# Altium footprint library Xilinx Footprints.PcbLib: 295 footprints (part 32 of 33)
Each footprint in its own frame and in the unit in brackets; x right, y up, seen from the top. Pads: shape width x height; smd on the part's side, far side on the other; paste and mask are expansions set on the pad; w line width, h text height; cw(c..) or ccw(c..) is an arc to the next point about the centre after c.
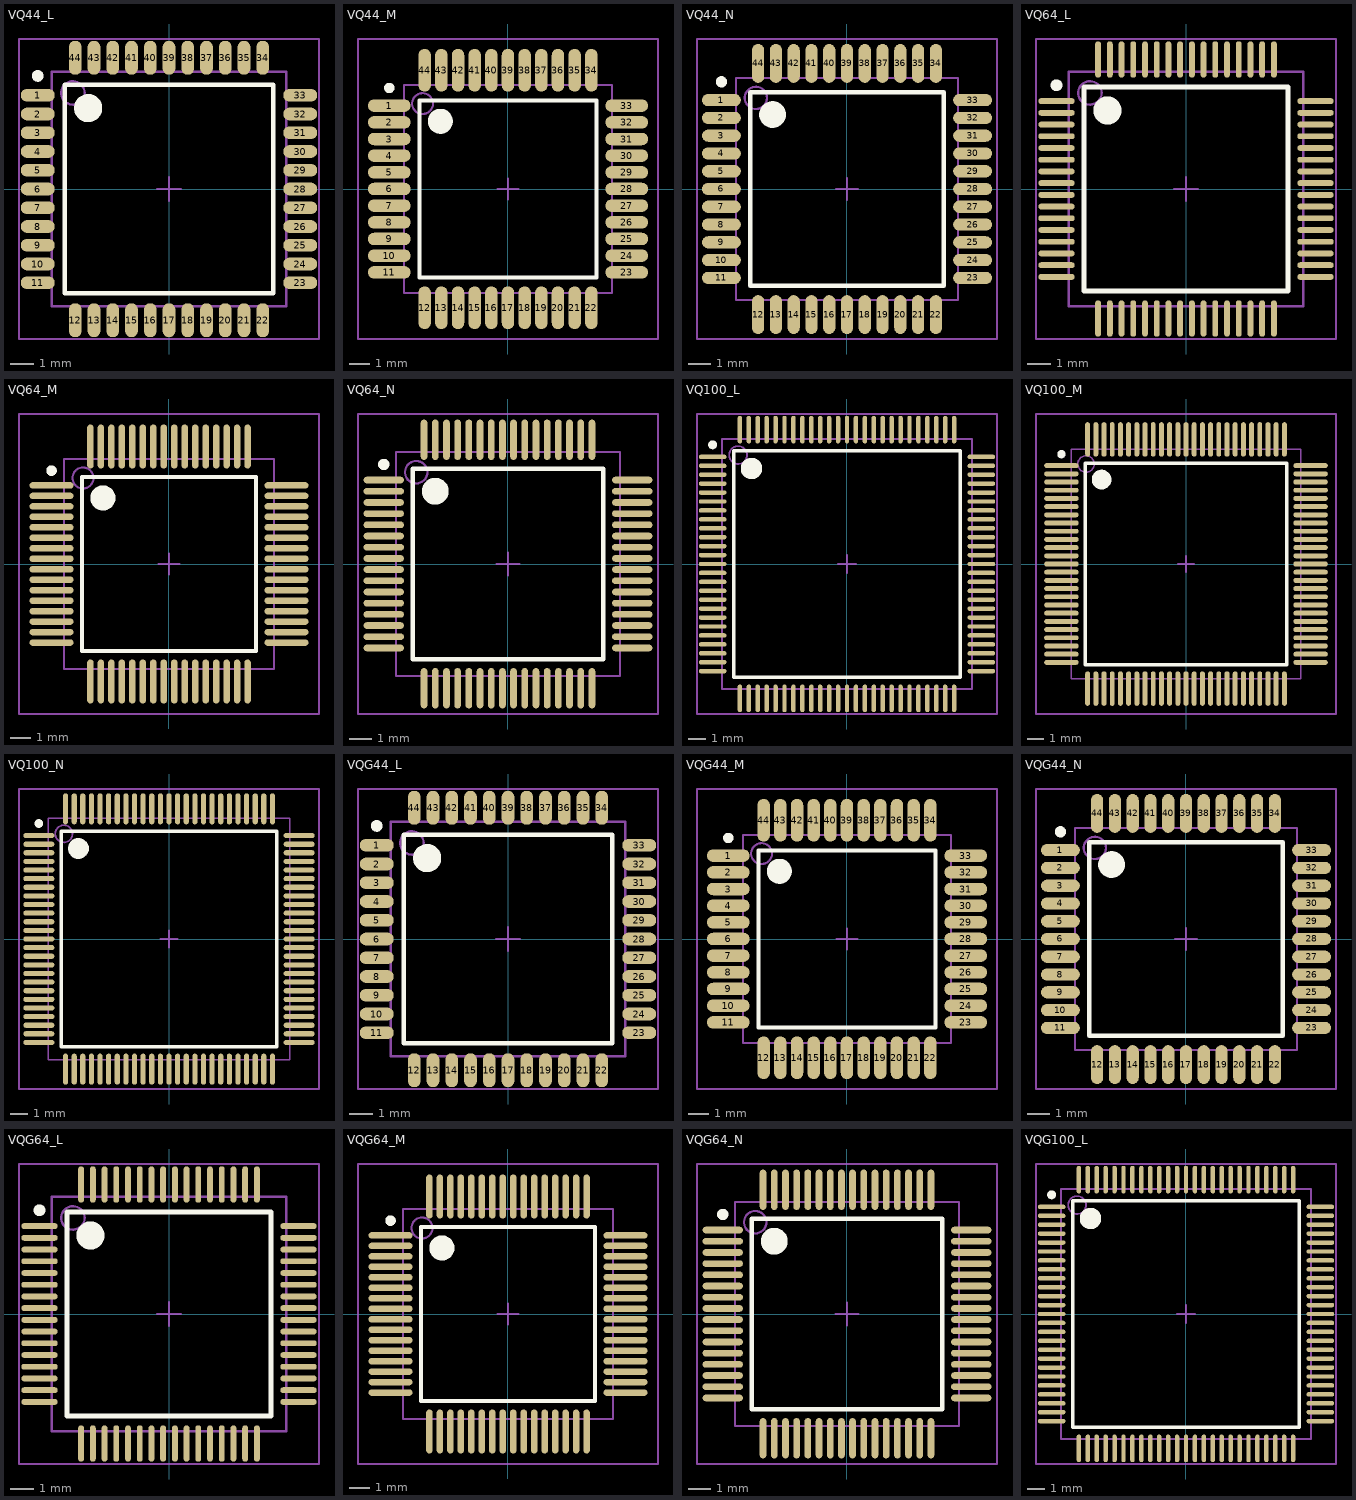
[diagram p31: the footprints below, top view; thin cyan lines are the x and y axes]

## VQ44_L [mm] "44-Pin Very Thin Quad Flat Pack (VQ44), IPC High Density"
height 1.2
pads (44):
  oval 1.45x0.55 smd: 1(-5.6,4) 2(-5.6,3.2) 3(-5.6,2.4) 4(-5.6,1.6) 5(-5.6,0.8) 6(-5.6,0) 7(-5.6,-0.8) 8(-5.6,-1.6) 9(-5.6,-2.4) 10(-5.6,-3.2) 11(-5.6,-4) 23(5.6,-4) 24(5.6,-3.2) 25(5.6,-2.4) 26(5.6,-1.6) 27(5.6,-0.8) 28(5.6,0) 29(5.6,0.8) 30(5.6,1.6) 31(5.6,2.4) 32(5.6,3.2) 33(5.6,4)
  oval 0.55x1.45 smd: 12(-4,-5.6) 13(-3.2,-5.6) 14(-2.4,-5.6) 15(-1.6,-5.6) 16(-0.8,-5.6) 17(0,-5.6) 18(0.8,-5.6) 19(1.6,-5.6) 20(2.4,-5.6) 21(3.2,-5.6) 22(4,-5.6) 34(4,5.6) 35(3.2,5.6) 36(2.4,5.6) 37(1.6,5.6) 38(0.8,5.6) 39(0,5.6) 40(-0.8,5.6) 41(-1.6,5.6) 42(-2.4,5.6) 43(-3.2,5.6) 44(-4,5.6)
Top Overlay:
  circle w0.6: c-3.45,3.45 r0.3
  circle w0.25: c-5.6,4.825 r0.125
  lines w0.2: -4.45,-4.45 4.45,-4.45 4.45,4.45 -4.45,4.45 -4.45,-4.45
Mechanical 13:
  circle w0.1: c-4.1,4.1 r0.5
  lines w0.1: -5,-5 5,-5 5,5 -5,5 -5,-5
Mechanical 15:
  lines w0.1: -0.5,0 0.5,0 ; 0,-0.5 0,0.5 ; -6.4,-6.4 6.4,-6.4 6.4,6.4 -6.4,6.4 -6.4,-6.4
3D body: height 1.2, standoff 0, extent -5,-5 5,5

## VQ44_M [mm] "44-Pin Very Thin Quad Flat Pack (VQ44), IPC Low Density"
height 1.2
pads (44):
  oval 2.05x0.6 smd: 1(-5.7,4) 2(-5.7,3.2) 3(-5.7,2.4) 4(-5.7,1.6) 5(-5.7,0.8) 6(-5.7,0) 7(-5.7,-0.8) 8(-5.7,-1.6) 9(-5.7,-2.4) 10(-5.7,-3.2) 11(-5.7,-4) 23(5.7,-4) 24(5.7,-3.2) 25(5.7,-2.4) 26(5.7,-1.6) 27(5.7,-0.8) 28(5.7,0) 29(5.7,0.8) 30(5.7,1.6) 31(5.7,2.4) 32(5.7,3.2) 33(5.7,4)
  oval 0.6x2.05 smd: 12(-4,-5.7) 13(-3.2,-5.7) 14(-2.4,-5.7) 15(-1.6,-5.7) 16(-0.8,-5.7) 17(0,-5.7) 18(0.8,-5.7) 19(1.6,-5.7) 20(2.4,-5.7) 21(3.2,-5.7) 22(4,-5.7) 34(4,5.7) 35(3.2,5.7) 36(2.4,5.7) 37(1.6,5.7) 38(0.8,5.7) 39(0,5.7) 40(-0.8,5.7) 41(-1.6,5.7) 42(-2.4,5.7) 43(-3.2,5.7) 44(-4,5.7)
Top Overlay:
  circle w0.6: c-3.25,3.25 r0.3
  circle w0.25: c-5.7,4.85 r0.125
  lines w0.2: -4.25,-4.25 4.25,-4.25 4.25,4.25 -4.25,4.25 -4.25,-4.25
Mechanical 13:
  circle w0.1: c-4.1,4.1 r0.5
  lines w0.1: -5,-5 5,-5 5,5 -5,5 -5,-5
Mechanical 15:
  lines w0.1: -0.5,0 0.5,0 ; 0,-0.5 0,0.5 ; -7.2,-7.2 7.2,-7.2 7.2,7.2 -7.2,7.2 -7.2,-7.2
3D body: height 1.2, standoff 0, extent -5,-5 5,5

## VQ44_N [mm] "44-Pin Very Thin Quad Flat Pack (VQ44), IPC Medium Density"
height 1.2
pads (44):
  oval 1.75x0.55 smd: 1(-5.65,4) 2(-5.65,3.2) 3(-5.65,2.4) 4(-5.65,1.6) 5(-5.65,0.8) 6(-5.65,0) 7(-5.65,-0.8) 8(-5.65,-1.6) 9(-5.65,-2.4) 10(-5.65,-3.2) 11(-5.65,-4) 23(5.65,-4) 24(5.65,-3.2) 25(5.65,-2.4) 26(5.65,-1.6) 27(5.65,-0.8) 28(5.65,0) 29(5.65,0.8) 30(5.65,1.6) 31(5.65,2.4) 32(5.65,3.2) 33(5.65,4)
  oval 0.55x1.75 smd: 12(-4,-5.65) 13(-3.2,-5.65) 14(-2.4,-5.65) 15(-1.6,-5.65) 16(-0.8,-5.65) 17(0,-5.65) 18(0.8,-5.65) 19(1.6,-5.65) 20(2.4,-5.65) 21(3.2,-5.65) 22(4,-5.65) 34(4,5.65) 35(3.2,5.65) 36(2.4,5.65) 37(1.6,5.65) 38(0.8,5.65) 39(0,5.65) 40(-0.8,5.65) 41(-1.6,5.65) 42(-2.4,5.65) 43(-3.2,5.65) 44(-4,5.65)
Top Overlay:
  circle w0.6: c-3.35,3.35 r0.3
  circle w0.25: c-5.65,4.825 r0.125
  lines w0.2: -4.35,-4.35 4.35,-4.35 4.35,4.35 -4.35,4.35 -4.35,-4.35
Mechanical 13:
  circle w0.1: c-4.1,4.1 r0.5
  lines w0.1: -5,-5 5,-5 5,5 -5,5 -5,-5
Mechanical 15:
  lines w0.1: -0.5,0 0.5,0 ; 0,-0.5 0,0.5 ; -6.75,-6.75 6.75,-6.75 6.75,6.75 -6.75,6.75 -6.75,-6.75
3D body: height 1.2, standoff 0, extent -5,-5 5,5

## VQ64_L [mm] "64-Pin Very Thin Quad Flat Pack (VQ64), IPC High Density"
height 1.2
pads (64):
  oval 1.55x0.25 smd: 1(-5.525,3.75) 2(-5.525,3.25) 3(-5.525,2.75) 4(-5.525,2.25) 5(-5.525,1.75) 6(-5.525,1.25) 7(-5.525,0.75) 8(-5.525,0.25) 9(-5.525,-0.25) 10(-5.525,-0.75) 11(-5.525,-1.25) 12(-5.525,-1.75) 13(-5.525,-2.25) 14(-5.525,-2.75) 15(-5.525,-3.25) 16(-5.525,-3.75) 33(5.525,-3.75) 34(5.525,-3.25) 35(5.525,-2.75) 36(5.525,-2.25) 37(5.525,-1.75) 38(5.525,-1.25) 39(5.525,-0.75) 40(5.525,-0.25) 41(5.525,0.25) 42(5.525,0.75) 43(5.525,1.25) 44(5.525,1.75) 45(5.525,2.25) 46(5.525,2.75) 47(5.525,3.25) 48(5.525,3.75)
  oval 0.25x1.55 smd: 17(-3.75,-5.525) 18(-3.25,-5.525) 19(-2.75,-5.525) 20(-2.25,-5.525) 21(-1.75,-5.525) 22(-1.25,-5.525) 23(-0.75,-5.525) 24(-0.25,-5.525) 25(0.25,-5.525) 26(0.75,-5.525) 27(1.25,-5.525) 28(1.75,-5.525) 29(2.25,-5.525) 30(2.75,-5.525) 31(3.25,-5.525) 32(3.75,-5.525) 49(3.75,5.525) 50(3.25,5.525) 51(2.75,5.525) 52(2.25,5.525) 53(1.75,5.525) 54(1.25,5.525) 55(0.75,5.525) 56(0.25,5.525) 57(-0.25,5.525) 58(-0.75,5.525) 59(-1.25,5.525) 60(-1.75,5.525) 61(-2.25,5.525) 62(-2.75,5.525) 63(-3.25,5.525) 64(-3.75,5.525)
Top Overlay:
  circle w0.6: c-3.35,3.35 r0.3
  circle w0.25: c-5.525,4.425 r0.125
  lines w0.2: -4.35,-4.35 4.35,-4.35 4.35,4.35 -4.35,4.35 -4.35,-4.35
Mechanical 13:
  circle w0.1: c-4.1,4.1 r0.5
  lines w0.1: -5,-5 5,-5 5,5 -5,5 -5,-5
Mechanical 15:
  lines w0.1: -0.5,0 0.5,0 ; 0,-0.5 0,0.5 ; -6.4,-6.4 6.4,-6.4 6.4,6.4 -6.4,6.4 -6.4,-6.4
3D body: height 1.2, standoff 0, extent -5,-5 5,5

## VQ64_M [mm] "64-Pin Very Thin Quad Flat Pack (VQ64), IPC Low Density"
height 1.2
pads (64):
  oval 2.1x0.3 smd: 1(-5.6,3.75) 2(-5.6,3.25) 3(-5.6,2.75) 4(-5.6,2.25) 5(-5.6,1.75) 6(-5.6,1.25) 7(-5.6,0.75) 8(-5.6,0.25) 9(-5.6,-0.25) 10(-5.6,-0.75) 11(-5.6,-1.25) 12(-5.6,-1.75) 13(-5.6,-2.25) 14(-5.6,-2.75) 15(-5.6,-3.25) 16(-5.6,-3.75) 33(5.6,-3.75) 34(5.6,-3.25) 35(5.6,-2.75) 36(5.6,-2.25) 37(5.6,-1.75) 38(5.6,-1.25) 39(5.6,-0.75) 40(5.6,-0.25) 41(5.6,0.25) 42(5.6,0.75) 43(5.6,1.25) 44(5.6,1.75) 45(5.6,2.25) 46(5.6,2.75) 47(5.6,3.25) 48(5.6,3.75)
  oval 0.3x2.1 smd: 17(-3.75,-5.6) 18(-3.25,-5.6) 19(-2.75,-5.6) 20(-2.25,-5.6) 21(-1.75,-5.6) 22(-1.25,-5.6) 23(-0.75,-5.6) 24(-0.25,-5.6) 25(0.25,-5.6) 26(0.75,-5.6) 27(1.25,-5.6) 28(1.75,-5.6) 29(2.25,-5.6) 30(2.75,-5.6) 31(3.25,-5.6) 32(3.75,-5.6) 49(3.75,5.6) 50(3.25,5.6) 51(2.75,5.6) 52(2.25,5.6) 53(1.75,5.6) 54(1.25,5.6) 55(0.75,5.6) 56(0.25,5.6) 57(-0.25,5.6) 58(-0.75,5.6) 59(-1.25,5.6) 60(-1.75,5.6) 61(-2.25,5.6) 62(-2.75,5.6) 63(-3.25,5.6) 64(-3.75,5.6)
Top Overlay:
  circle w0.6: c-3.15,3.15 r0.3
  circle w0.25: c-5.6,4.45 r0.125
  lines w0.2: -4.15,-4.15 4.15,-4.15 4.15,4.15 -4.15,4.15 -4.15,-4.15
Mechanical 13:
  circle w0.1: c-4.1,4.1 r0.5
  lines w0.1: -5,-5 5,-5 5,5 -5,5 -5,-5
Mechanical 15:
  lines w0.1: -0.5,0 0.5,0 ; 0,-0.5 0,0.5 ; -7.15,-7.15 7.15,-7.15 7.15,7.15 -7.15,7.15 -7.15,-7.15
3D body: height 1.2, standoff 0, extent -5,-5 5,5

## VQ64_N [mm] "64-Pin Very Thin Quad Flat Pack (VQ64), IPC Medium Density"
height 1.2
pads (64):
  oval 1.8x0.3 smd: 1(-5.55,3.75) 2(-5.55,3.25) 3(-5.55,2.75) 4(-5.55,2.25) 5(-5.55,1.75) 6(-5.55,1.25) 7(-5.55,0.75) 8(-5.55,0.25) 9(-5.55,-0.25) 10(-5.55,-0.75) 11(-5.55,-1.25) 12(-5.55,-1.75) 13(-5.55,-2.25) 14(-5.55,-2.75) 15(-5.55,-3.25) 16(-5.55,-3.75) 33(5.55,-3.75) 34(5.55,-3.25) 35(5.55,-2.75) 36(5.55,-2.25) 37(5.55,-1.75) 38(5.55,-1.25) 39(5.55,-0.75) 40(5.55,-0.25) 41(5.55,0.25) 42(5.55,0.75) 43(5.55,1.25) 44(5.55,1.75) 45(5.55,2.25) 46(5.55,2.75) 47(5.55,3.25) 48(5.55,3.75)
  oval 0.3x1.8 smd: 17(-3.75,-5.55) 18(-3.25,-5.55) 19(-2.75,-5.55) 20(-2.25,-5.55) 21(-1.75,-5.55) 22(-1.25,-5.55) 23(-0.75,-5.55) 24(-0.25,-5.55) 25(0.25,-5.55) 26(0.75,-5.55) 27(1.25,-5.55) 28(1.75,-5.55) 29(2.25,-5.55) 30(2.75,-5.55) 31(3.25,-5.55) 32(3.75,-5.55) 49(3.75,5.55) 50(3.25,5.55) 51(2.75,5.55) 52(2.25,5.55) 53(1.75,5.55) 54(1.25,5.55) 55(0.75,5.55) 56(0.25,5.55) 57(-0.25,5.55) 58(-0.75,5.55) 59(-1.25,5.55) 60(-1.75,5.55) 61(-2.25,5.55) 62(-2.75,5.55) 63(-3.25,5.55) 64(-3.75,5.55)
Top Overlay:
  circle w0.25: c-5.55,4.45 r0.125
  circle w0.6: c-3.25,3.25 r0.3
  lines w0.2: -4.25,-4.25 -4.25,4.25 4.25,4.25 4.25,-4.25 -4.25,-4.25
Mechanical 13:
  circle w0.1: c-4.1,4.1 r0.5
  lines w0.1: -5,-5 -5,5 5,5 5,-5 -5,-5
Mechanical 15:
  lines w0.1: -0.5,0 0.5,0 ; 0,-0.5 0,0.5 ; -6.7,-6.7 -6.7,6.7 6.7,6.7 6.7,-6.7 -6.7,-6.7
3D body: height 1.2, standoff 0, extent -5,-5 5,5

## VQ100_L [mm] "100-Pin Very Thin Quad Flat Pack (VQ100), IPC High Density"
height 1.2
pads (100):
  oval 1.55x0.25 smd: 1(-7.525,6) 2(-7.525,5.5) 3(-7.525,5) 4(-7.525,4.5) 5(-7.525,4) 6(-7.525,3.5) 7(-7.525,3) 8(-7.525,2.5) 9(-7.525,2) 10(-7.525,1.5) 11(-7.525,1) 12(-7.525,0.5) 13(-7.525,0) 14(-7.525,-0.5) 15(-7.525,-1) 16(-7.525,-1.5) 17(-7.525,-2) 18(-7.525,-2.5) 19(-7.525,-3) 20(-7.525,-3.5) 21(-7.525,-4) 22(-7.525,-4.5) 23(-7.525,-5) 24(-7.525,-5.5) 25(-7.525,-6) 51(7.525,-6) 52(7.525,-5.5) 53(7.525,-5) 54(7.525,-4.5) 55(7.525,-4) 56(7.525,-3.5) 57(7.525,-3) 58(7.525,-2.5) 59(7.525,-2) 60(7.525,-1.5) 61(7.525,-1) 62(7.525,-0.5) 63(7.525,0) 64(7.525,0.5) 65(7.525,1) 66(7.525,1.5) 67(7.525,2) 68(7.525,2.5) 69(7.525,3) 70(7.525,3.5) 71(7.525,4) 72(7.525,4.5) 73(7.525,5) 74(7.525,5.5) 75(7.525,6)
  oval 0.25x1.55 smd: 26(-6,-7.525) 27(-5.5,-7.525) 28(-5,-7.525) 29(-4.5,-7.525) 30(-4,-7.525) 31(-3.5,-7.525) 32(-3,-7.525) 33(-2.5,-7.525) 34(-2,-7.525) 35(-1.5,-7.525) 36(-1,-7.525) 37(-0.5,-7.525) 38(0,-7.525) 39(0.5,-7.525) 40(1,-7.525) 41(1.5,-7.525) 42(2,-7.525) 43(2.5,-7.525) 44(3,-7.525) 45(3.5,-7.525) 46(4,-7.525) 47(4.5,-7.525) 48(5,-7.525) 49(5.5,-7.525) 50(6,-7.525) 76(6,7.525) 77(5.5,7.525) 78(5,7.525) 79(4.5,7.525) 80(4,7.525) 81(3.5,7.525) 82(3,7.525) 83(2.5,7.525) 84(2,7.525) 85(1.5,7.525) 86(1,7.525) 87(0.5,7.525) 88(0,7.525) 89(-0.5,7.525) 90(-1,7.525) 91(-1.5,7.525) 92(-2,7.525) 93(-2.5,7.525) 94(-3,7.525) 95(-3.5,7.525) 96(-4,7.525) 97(-4.5,7.525) 98(-5,7.525) 99(-5.5,7.525) 100(-6,7.525)
Top Overlay:
  circle w0.6: c-5.35,5.35 r0.3
  circle w0.25: c-7.525,6.675 r0.125
  lines w0.2: -6.35,-6.35 6.35,-6.35 6.35,6.35 -6.35,6.35 -6.35,-6.35
Mechanical 13:
  circle w0.1: c-6.1,6.1 r0.5
  lines w0.1: -7,-7 7,-7 7,7 -7,7 -7,-7
Mechanical 15:
  lines w0.1: -0.5,0 0.5,0 ; 0,-0.5 0,0.5 ; -8.4,-8.4 8.4,-8.4 8.4,8.4 -8.4,8.4 -8.4,-8.4
3D body: height 1.2, standoff 0, extent -7,-7 7,7

## VQ100_M [mm] "100-Pin Very Thin Quad Flat Pack (VQ100), IPC Low Density"
height 1.2
pads (100):
  oval 2.1x0.3 smd: 1(-7.6,6) 2(-7.6,5.5) 3(-7.6,5) 4(-7.6,4.5) 5(-7.6,4) 6(-7.6,3.5) 7(-7.6,3) 8(-7.6,2.5) 9(-7.6,2) 10(-7.6,1.5) 11(-7.6,1) 12(-7.6,0.5) 13(-7.6,0) 14(-7.6,-0.5) 15(-7.6,-1) 16(-7.6,-1.5) 17(-7.6,-2) 18(-7.6,-2.5) 19(-7.6,-3) 20(-7.6,-3.5) 21(-7.6,-4) 22(-7.6,-4.5) 23(-7.6,-5) 24(-7.6,-5.5) 25(-7.6,-6) 51(7.6,-6) 52(7.6,-5.5) 53(7.6,-5) 54(7.6,-4.5) 55(7.6,-4) 56(7.6,-3.5) 57(7.6,-3) 58(7.6,-2.5) 59(7.6,-2) 60(7.6,-1.5) 61(7.6,-1) 62(7.6,-0.5) 63(7.6,0) 64(7.6,0.5) 65(7.6,1) 66(7.6,1.5) 67(7.6,2) 68(7.6,2.5) 69(7.6,3) 70(7.6,3.5) 71(7.6,4) 72(7.6,4.5) 73(7.6,5) 74(7.6,5.5) 75(7.6,6)
  oval 0.3x2.1 smd: 26(-6,-7.6) 27(-5.5,-7.6) 28(-5,-7.6) 29(-4.5,-7.6) 30(-4,-7.6) 31(-3.5,-7.6) 32(-3,-7.6) 33(-2.5,-7.6) 34(-2,-7.6) 35(-1.5,-7.6) 36(-1,-7.6) 37(-0.5,-7.6) 38(0,-7.6) 39(0.5,-7.6) 40(1,-7.6) 41(1.5,-7.6) 42(2,-7.6) 43(2.5,-7.6) 44(3,-7.6) 45(3.5,-7.6) 46(4,-7.6) 47(4.5,-7.6) 48(5,-7.6) 49(5.5,-7.6) 50(6,-7.6) 76(6,7.6) 77(5.5,7.6) 78(5,7.6) 79(4.5,7.6) 80(4,7.6) 81(3.5,7.6) 82(3,7.6) 83(2.5,7.6) 84(2,7.6) 85(1.5,7.6) 86(1,7.6) 87(0.5,7.6) 88(0,7.6) 89(-0.5,7.6) 90(-1,7.6) 91(-1.5,7.6) 92(-2,7.6) 93(-2.5,7.6) 94(-3,7.6) 95(-3.5,7.6) 96(-4,7.6) 97(-4.5,7.6) 98(-5,7.6) 99(-5.5,7.6) 100(-6,7.6)
Top Overlay:
  circle w0.6: c-5.15,5.15 r0.3
  circle w0.25: c-7.6,6.7 r0.125
  lines w0.2: -6.15,-6.15 6.15,-6.15 6.15,6.15 -6.15,6.15 -6.15,-6.15
Mechanical 13:
  circle w0.1: c-6.1,6.1 r0.5
  lines w0.1: -7,-7 7,-7 7,7 -7,7 -7,-7
Mechanical 15:
  lines w0.1: -0.5,0 0.5,0 ; 0,-0.5 0,0.5 ; -9.15,-9.15 9.15,-9.15 9.15,9.15 -9.15,9.15 -9.15,-9.15
3D body: height 1.2, standoff 0, extent -7,-7 7,7

## VQ100_N [mm] "100-Pin Very Thin Quad Flat Pack (VQ100), IPC Medium Density"
height 1.2
pads (100):
  oval 1.8x0.3 smd: 1(-7.55,6) 2(-7.55,5.5) 3(-7.55,5) 4(-7.55,4.5) 5(-7.55,4) 6(-7.55,3.5) 7(-7.55,3) 8(-7.55,2.5) 9(-7.55,2) 10(-7.55,1.5) 11(-7.55,1) 12(-7.55,0.5) 13(-7.55,0) 14(-7.55,-0.5) 15(-7.55,-1) 16(-7.55,-1.5) 17(-7.55,-2) 18(-7.55,-2.5) 19(-7.55,-3) 20(-7.55,-3.5) 21(-7.55,-4) 22(-7.55,-4.5) 23(-7.55,-5) 24(-7.55,-5.5) 25(-7.55,-6) 51(7.55,-6) 52(7.55,-5.5) 53(7.55,-5) 54(7.55,-4.5) 55(7.55,-4) 56(7.55,-3.5) 57(7.55,-3) 58(7.55,-2.5) 59(7.55,-2) 60(7.55,-1.5) 61(7.55,-1) 62(7.55,-0.5) 63(7.55,0) 64(7.55,0.5) 65(7.55,1) 66(7.55,1.5) 67(7.55,2) 68(7.55,2.5) 69(7.55,3) 70(7.55,3.5) 71(7.55,4) 72(7.55,4.5) 73(7.55,5) 74(7.55,5.5) 75(7.55,6)
  oval 0.3x1.8 smd: 26(-6,-7.55) 27(-5.5,-7.55) 28(-5,-7.55) 29(-4.5,-7.55) 30(-4,-7.55) 31(-3.5,-7.55) 32(-3,-7.55) 33(-2.5,-7.55) 34(-2,-7.55) 35(-1.5,-7.55) 36(-1,-7.55) 37(-0.5,-7.55) 38(0,-7.55) 39(0.5,-7.55) 40(1,-7.55) 41(1.5,-7.55) 42(2,-7.55) 43(2.5,-7.55) 44(3,-7.55) 45(3.5,-7.55) 46(4,-7.55) 47(4.5,-7.55) 48(5,-7.55) 49(5.5,-7.55) 50(6,-7.55) 76(6,7.55) 77(5.5,7.55) 78(5,7.55) 79(4.5,7.55) 80(4,7.55) 81(3.5,7.55) 82(3,7.55) 83(2.5,7.55) 84(2,7.55) 85(1.5,7.55) 86(1,7.55) 87(0.5,7.55) 88(0,7.55) 89(-0.5,7.55) 90(-1,7.55) 91(-1.5,7.55) 92(-2,7.55) 93(-2.5,7.55) 94(-3,7.55) 95(-3.5,7.55) 96(-4,7.55) 97(-4.5,7.55) 98(-5,7.55) 99(-5.5,7.55) 100(-6,7.55)
Top Overlay:
  circle w0.6: c-5.25,5.25 r0.3
  circle w0.25: c-7.55,6.7 r0.125
  lines w0.2: -6.25,-6.25 6.25,-6.25 6.25,6.25 -6.25,6.25 -6.25,-6.25
Mechanical 13:
  circle w0.1: c-6.1,6.1 r0.5
  lines w0.1: -7,-7 7,-7 7,7 -7,7 -7,-7
Mechanical 15:
  lines w0.1: -0.5,0 0.5,0 ; 0,-0.5 0,0.5 ; -8.7,-8.7 8.7,-8.7 8.7,8.7 -8.7,8.7 -8.7,-8.7
3D body: height 1.2, standoff 0, extent -7,-7 7,7

## VQG44_L [mm] "44-Pin Very Thin Quad Flat Pack (VQG44) - Pb-Free, IPC High Density"
height 1.2
pads (44):
  oval 1.45x0.55 smd: 1(-5.6,4) 2(-5.6,3.2) 3(-5.6,2.4) 4(-5.6,1.6) 5(-5.6,0.8) 6(-5.6,0) 7(-5.6,-0.8) 8(-5.6,-1.6) 9(-5.6,-2.4) 10(-5.6,-3.2) 11(-5.6,-4) 23(5.6,-4) 24(5.6,-3.2) 25(5.6,-2.4) 26(5.6,-1.6) 27(5.6,-0.8) 28(5.6,0) 29(5.6,0.8) 30(5.6,1.6) 31(5.6,2.4) 32(5.6,3.2) 33(5.6,4)
  oval 0.55x1.45 smd: 12(-4,-5.6) 13(-3.2,-5.6) 14(-2.4,-5.6) 15(-1.6,-5.6) 16(-0.8,-5.6) 17(0,-5.6) 18(0.8,-5.6) 19(1.6,-5.6) 20(2.4,-5.6) 21(3.2,-5.6) 22(4,-5.6) 34(4,5.6) 35(3.2,5.6) 36(2.4,5.6) 37(1.6,5.6) 38(0.8,5.6) 39(0,5.6) 40(-0.8,5.6) 41(-1.6,5.6) 42(-2.4,5.6) 43(-3.2,5.6) 44(-4,5.6)
Top Overlay:
  circle w0.6: c-3.45,3.45 r0.3
  circle w0.25: c-5.6,4.825 r0.125
  lines w0.2: -4.45,-4.45 4.45,-4.45 4.45,4.45 -4.45,4.45 -4.45,-4.45
Mechanical 13:
  circle w0.1: c-4.1,4.1 r0.5
  lines w0.1: -5,-5 5,-5 5,5 -5,5 -5,-5
Mechanical 15:
  lines w0.1: -0.5,0 0.5,0 ; 0,-0.5 0,0.5 ; -6.4,-6.4 6.4,-6.4 6.4,6.4 -6.4,6.4 -6.4,-6.4
3D body: height 1.2, standoff 0, extent -5,-5 5,5

## VQG44_M [mm] "44-Pin Very Thin Quad Flat Pack (VQG44) - Pb-Free, IPC Low Density"
height 1.2
pads (44):
  oval 2.05x0.6 smd: 1(-5.7,4) 2(-5.7,3.2) 3(-5.7,2.4) 4(-5.7,1.6) 5(-5.7,0.8) 6(-5.7,0) 7(-5.7,-0.8) 8(-5.7,-1.6) 9(-5.7,-2.4) 10(-5.7,-3.2) 11(-5.7,-4) 23(5.7,-4) 24(5.7,-3.2) 25(5.7,-2.4) 26(5.7,-1.6) 27(5.7,-0.8) 28(5.7,0) 29(5.7,0.8) 30(5.7,1.6) 31(5.7,2.4) 32(5.7,3.2) 33(5.7,4)
  oval 0.6x2.05 smd: 12(-4,-5.7) 13(-3.2,-5.7) 14(-2.4,-5.7) 15(-1.6,-5.7) 16(-0.8,-5.7) 17(0,-5.7) 18(0.8,-5.7) 19(1.6,-5.7) 20(2.4,-5.7) 21(3.2,-5.7) 22(4,-5.7) 34(4,5.7) 35(3.2,5.7) 36(2.4,5.7) 37(1.6,5.7) 38(0.8,5.7) 39(0,5.7) 40(-0.8,5.7) 41(-1.6,5.7) 42(-2.4,5.7) 43(-3.2,5.7) 44(-4,5.7)
Top Overlay:
  circle w0.6: c-3.25,3.25 r0.3
  circle w0.25: c-5.7,4.85 r0.125
  lines w0.2: -4.25,-4.25 4.25,-4.25 4.25,4.25 -4.25,4.25 -4.25,-4.25
Mechanical 13:
  circle w0.1: c-4.1,4.1 r0.5
  lines w0.1: -5,-5 5,-5 5,5 -5,5 -5,-5
Mechanical 15:
  lines w0.1: -0.5,0 0.5,0 ; 0,-0.5 0,0.5 ; -7.2,-7.2 7.2,-7.2 7.2,7.2 -7.2,7.2 -7.2,-7.2
3D body: height 1.2, standoff 0, extent -5,-5 5,5

## VQG44_N [mm] "44-Pin Very Thin Quad Flat Pack (VQG44) - Pb-Free, IPC Medium Density"
height 1.2
pads (44):
  oval 1.75x0.55 smd: 1(-5.65,4) 2(-5.65,3.2) 3(-5.65,2.4) 4(-5.65,1.6) 5(-5.65,0.8) 6(-5.65,0) 7(-5.65,-0.8) 8(-5.65,-1.6) 9(-5.65,-2.4) 10(-5.65,-3.2) 11(-5.65,-4) 23(5.65,-4) 24(5.65,-3.2) 25(5.65,-2.4) 26(5.65,-1.6) 27(5.65,-0.8) 28(5.65,0) 29(5.65,0.8) 30(5.65,1.6) 31(5.65,2.4) 32(5.65,3.2) 33(5.65,4)
  oval 0.55x1.75 smd: 12(-4,-5.65) 13(-3.2,-5.65) 14(-2.4,-5.65) 15(-1.6,-5.65) 16(-0.8,-5.65) 17(0,-5.65) 18(0.8,-5.65) 19(1.6,-5.65) 20(2.4,-5.65) 21(3.2,-5.65) 22(4,-5.65) 34(4,5.65) 35(3.2,5.65) 36(2.4,5.65) 37(1.6,5.65) 38(0.8,5.65) 39(0,5.65) 40(-0.8,5.65) 41(-1.6,5.65) 42(-2.4,5.65) 43(-3.2,5.65) 44(-4,5.65)
Top Overlay:
  circle w0.6: c-3.35,3.35 r0.3
  circle w0.25: c-5.65,4.825 r0.125
  lines w0.2: -4.35,-4.35 4.35,-4.35 4.35,4.35 -4.35,4.35 -4.35,-4.35
Mechanical 13:
  circle w0.1: c-4.1,4.1 r0.5
  lines w0.1: -5,-5 5,-5 5,5 -5,5 -5,-5
Mechanical 15:
  lines w0.1: -0.5,0 0.5,0 ; 0,-0.5 0,0.5 ; -6.75,-6.75 6.75,-6.75 6.75,6.75 -6.75,6.75 -6.75,-6.75
3D body: height 1.2, standoff 0, extent -5,-5 5,5

## VQG64_L [mm] "64-Pin Very Thin Quad Flat Pack (VQG64) - Pb-Free, IPC High Density"
height 1.2
pads (64):
  oval 1.55x0.25 smd: 1(-5.525,3.75) 2(-5.525,3.25) 3(-5.525,2.75) 4(-5.525,2.25) 5(-5.525,1.75) 6(-5.525,1.25) 7(-5.525,0.75) 8(-5.525,0.25) 9(-5.525,-0.25) 10(-5.525,-0.75) 11(-5.525,-1.25) 12(-5.525,-1.75) 13(-5.525,-2.25) 14(-5.525,-2.75) 15(-5.525,-3.25) 16(-5.525,-3.75) 33(5.525,-3.75) 34(5.525,-3.25) 35(5.525,-2.75) 36(5.525,-2.25) 37(5.525,-1.75) 38(5.525,-1.25) 39(5.525,-0.75) 40(5.525,-0.25) 41(5.525,0.25) 42(5.525,0.75) 43(5.525,1.25) 44(5.525,1.75) 45(5.525,2.25) 46(5.525,2.75) 47(5.525,3.25) 48(5.525,3.75)
  oval 0.25x1.55 smd: 17(-3.75,-5.525) 18(-3.25,-5.525) 19(-2.75,-5.525) 20(-2.25,-5.525) 21(-1.75,-5.525) 22(-1.25,-5.525) 23(-0.75,-5.525) 24(-0.25,-5.525) 25(0.25,-5.525) 26(0.75,-5.525) 27(1.25,-5.525) 28(1.75,-5.525) 29(2.25,-5.525) 30(2.75,-5.525) 31(3.25,-5.525) 32(3.75,-5.525) 49(3.75,5.525) 50(3.25,5.525) 51(2.75,5.525) 52(2.25,5.525) 53(1.75,5.525) 54(1.25,5.525) 55(0.75,5.525) 56(0.25,5.525) 57(-0.25,5.525) 58(-0.75,5.525) 59(-1.25,5.525) 60(-1.75,5.525) 61(-2.25,5.525) 62(-2.75,5.525) 63(-3.25,5.525) 64(-3.75,5.525)
Top Overlay:
  circle w0.6: c-3.35,3.35 r0.3
  circle w0.25: c-5.525,4.425 r0.125
  lines w0.2: -4.35,-4.35 4.35,-4.35 4.35,4.35 -4.35,4.35 -4.35,-4.35
Mechanical 13:
  circle w0.1: c-4.1,4.1 r0.5
  lines w0.1: -5,-5 5,-5 5,5 -5,5 -5,-5
Mechanical 15:
  lines w0.1: -0.5,0 0.5,0 ; 0,-0.5 0,0.5 ; -6.4,-6.4 6.4,-6.4 6.4,6.4 -6.4,6.4 -6.4,-6.4
3D body: height 1.2, standoff 0, extent -5,-5 5,5

## VQG64_M [mm] "64-Pin Very Thin Quad Flat Pack (VQG64) - Pb-Free, IPC Low Density"
height 1.2
pads (64):
  oval 2.1x0.3 smd: 1(-5.6,3.75) 2(-5.6,3.25) 3(-5.6,2.75) 4(-5.6,2.25) 5(-5.6,1.75) 6(-5.6,1.25) 7(-5.6,0.75) 8(-5.6,0.25) 9(-5.6,-0.25) 10(-5.6,-0.75) 11(-5.6,-1.25) 12(-5.6,-1.75) 13(-5.6,-2.25) 14(-5.6,-2.75) 15(-5.6,-3.25) 16(-5.6,-3.75) 33(5.6,-3.75) 34(5.6,-3.25) 35(5.6,-2.75) 36(5.6,-2.25) 37(5.6,-1.75) 38(5.6,-1.25) 39(5.6,-0.75) 40(5.6,-0.25) 41(5.6,0.25) 42(5.6,0.75) 43(5.6,1.25) 44(5.6,1.75) 45(5.6,2.25) 46(5.6,2.75) 47(5.6,3.25) 48(5.6,3.75)
  oval 0.3x2.1 smd: 17(-3.75,-5.6) 18(-3.25,-5.6) 19(-2.75,-5.6) 20(-2.25,-5.6) 21(-1.75,-5.6) 22(-1.25,-5.6) 23(-0.75,-5.6) 24(-0.25,-5.6) 25(0.25,-5.6) 26(0.75,-5.6) 27(1.25,-5.6) 28(1.75,-5.6) 29(2.25,-5.6) 30(2.75,-5.6) 31(3.25,-5.6) 32(3.75,-5.6) 49(3.75,5.6) 50(3.25,5.6) 51(2.75,5.6) 52(2.25,5.6) 53(1.75,5.6) 54(1.25,5.6) 55(0.75,5.6) 56(0.25,5.6) 57(-0.25,5.6) 58(-0.75,5.6) 59(-1.25,5.6) 60(-1.75,5.6) 61(-2.25,5.6) 62(-2.75,5.6) 63(-3.25,5.6) 64(-3.75,5.6)
Top Overlay:
  circle w0.6: c-3.15,3.15 r0.3
  circle w0.25: c-5.6,4.45 r0.125
  lines w0.2: -4.15,-4.15 4.15,-4.15 4.15,4.15 -4.15,4.15 -4.15,-4.15
Mechanical 13:
  circle w0.1: c-4.1,4.1 r0.5
  lines w0.1: -5,-5 5,-5 5,5 -5,5 -5,-5
Mechanical 15:
  lines w0.1: -0.5,0 0.5,0 ; 0,-0.5 0,0.5 ; -7.15,-7.15 7.15,-7.15 7.15,7.15 -7.15,7.15 -7.15,-7.15
3D body: height 1.2, standoff 0, extent -5,-5 5,5

## VQG64_N [mm] "64-Pin Very Thin Quad Flat Pack (VQG64) - Pb-Free, IPC Medium Density"
height 1.2
pads (64):
  oval 1.8x0.3 smd: 1(-5.55,3.75) 2(-5.55,3.25) 3(-5.55,2.75) 4(-5.55,2.25) 5(-5.55,1.75) 6(-5.55,1.25) 7(-5.55,0.75) 8(-5.55,0.25) 9(-5.55,-0.25) 10(-5.55,-0.75) 11(-5.55,-1.25) 12(-5.55,-1.75) 13(-5.55,-2.25) 14(-5.55,-2.75) 15(-5.55,-3.25) 16(-5.55,-3.75) 33(5.55,-3.75) 34(5.55,-3.25) 35(5.55,-2.75) 36(5.55,-2.25) 37(5.55,-1.75) 38(5.55,-1.25) 39(5.55,-0.75) 40(5.55,-0.25) 41(5.55,0.25) 42(5.55,0.75) 43(5.55,1.25) 44(5.55,1.75) 45(5.55,2.25) 46(5.55,2.75) 47(5.55,3.25) 48(5.55,3.75)
  oval 0.3x1.8 smd: 17(-3.75,-5.55) 18(-3.25,-5.55) 19(-2.75,-5.55) 20(-2.25,-5.55) 21(-1.75,-5.55) 22(-1.25,-5.55) 23(-0.75,-5.55) 24(-0.25,-5.55) 25(0.25,-5.55) 26(0.75,-5.55) 27(1.25,-5.55) 28(1.75,-5.55) 29(2.25,-5.55) 30(2.75,-5.55) 31(3.25,-5.55) 32(3.75,-5.55) 49(3.75,5.55) 50(3.25,5.55) 51(2.75,5.55) 52(2.25,5.55) 53(1.75,5.55) 54(1.25,5.55) 55(0.75,5.55) 56(0.25,5.55) 57(-0.25,5.55) 58(-0.75,5.55) 59(-1.25,5.55) 60(-1.75,5.55) 61(-2.25,5.55) 62(-2.75,5.55) 63(-3.25,5.55) 64(-3.75,5.55)
Top Overlay:
  circle w0.25: c-5.55,4.45 r0.125
  circle w0.6: c-3.25,3.25 r0.3
  lines w0.2: -4.25,-4.25 -4.25,4.25 4.25,4.25 4.25,-4.25 -4.25,-4.25
Mechanical 13:
  circle w0.1: c-4.1,4.1 r0.5
  lines w0.1: -5,-5 -5,5 5,5 5,-5 -5,-5
Mechanical 15:
  lines w0.1: -0.5,0 0.5,0 ; 0,-0.5 0,0.5 ; -6.7,-6.7 -6.7,6.7 6.7,6.7 6.7,-6.7 -6.7,-6.7
3D body: height 1.2, standoff 0, extent -5,-5 5,5

## VQG100_L [mm] "100-Pin Very Thin Quad Flat Pack (VQG100) - Pb-Free, IPC High Density"
height 1.2
pads (100):
  oval 1.55x0.25 smd: 1(-7.525,6) 2(-7.525,5.5) 3(-7.525,5) 4(-7.525,4.5) 5(-7.525,4) 6(-7.525,3.5) 7(-7.525,3) 8(-7.525,2.5) 9(-7.525,2) 10(-7.525,1.5) 11(-7.525,1) 12(-7.525,0.5) 13(-7.525,0) 14(-7.525,-0.5) 15(-7.525,-1) 16(-7.525,-1.5) 17(-7.525,-2) 18(-7.525,-2.5) 19(-7.525,-3) 20(-7.525,-3.5) 21(-7.525,-4) 22(-7.525,-4.5) 23(-7.525,-5) 24(-7.525,-5.5) 25(-7.525,-6) 51(7.525,-6) 52(7.525,-5.5) 53(7.525,-5) 54(7.525,-4.5) 55(7.525,-4) 56(7.525,-3.5) 57(7.525,-3) 58(7.525,-2.5) 59(7.525,-2) 60(7.525,-1.5) 61(7.525,-1) 62(7.525,-0.5) 63(7.525,0) 64(7.525,0.5) 65(7.525,1) 66(7.525,1.5) 67(7.525,2) 68(7.525,2.5) 69(7.525,3) 70(7.525,3.5) 71(7.525,4) 72(7.525,4.5) 73(7.525,5) 74(7.525,5.5) 75(7.525,6)
  oval 0.25x1.55 smd: 26(-6,-7.525) 27(-5.5,-7.525) 28(-5,-7.525) 29(-4.5,-7.525) 30(-4,-7.525) 31(-3.5,-7.525) 32(-3,-7.525) 33(-2.5,-7.525) 34(-2,-7.525) 35(-1.5,-7.525) 36(-1,-7.525) 37(-0.5,-7.525) 38(0,-7.525) 39(0.5,-7.525) 40(1,-7.525) 41(1.5,-7.525) 42(2,-7.525) 43(2.5,-7.525) 44(3,-7.525) 45(3.5,-7.525) 46(4,-7.525) 47(4.5,-7.525) 48(5,-7.525) 49(5.5,-7.525) 50(6,-7.525) 76(6,7.525) 77(5.5,7.525) 78(5,7.525) 79(4.5,7.525) 80(4,7.525) 81(3.5,7.525) 82(3,7.525) 83(2.5,7.525) 84(2,7.525) 85(1.5,7.525) 86(1,7.525) 87(0.5,7.525) 88(0,7.525) 89(-0.5,7.525) 90(-1,7.525) 91(-1.5,7.525) 92(-2,7.525) 93(-2.5,7.525) 94(-3,7.525) 95(-3.5,7.525) 96(-4,7.525) 97(-4.5,7.525) 98(-5,7.525) 99(-5.5,7.525) 100(-6,7.525)
Top Overlay:
  circle w0.6: c-5.35,5.35 r0.3
  circle w0.25: c-7.525,6.675 r0.125
  lines w0.2: -6.35,-6.35 6.35,-6.35 6.35,6.35 -6.35,6.35 -6.35,-6.35
Mechanical 13:
  circle w0.1: c-6.1,6.1 r0.5
  lines w0.1: -7,-7 7,-7 7,7 -7,7 -7,-7
Mechanical 15:
  lines w0.1: -0.5,0 0.5,0 ; 0,-0.5 0,0.5 ; -8.4,-8.4 8.4,-8.4 8.4,8.4 -8.4,8.4 -8.4,-8.4
3D body: height 1.2, standoff 0, extent -7,-7 7,7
